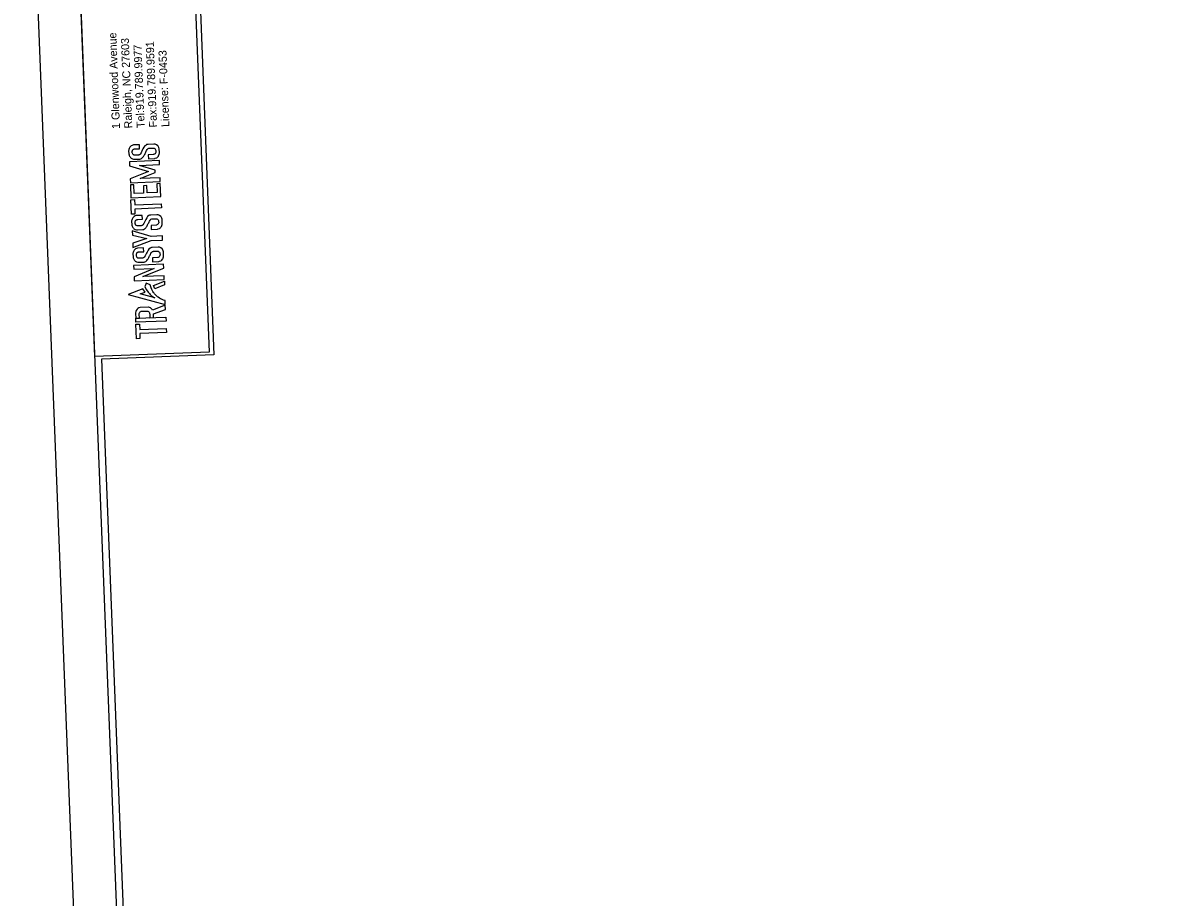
# Model space of a CAD drawing. Extents: x 1627855 to 1629021, y 762567 to 764488.
# Drawn here: x 1627855 to 1628524, y 763528 to 764036 of the extents above; entities that cross this region are included whole.
import ezdxf

# ---------------------------------------------------------------- set-up
doc = ezdxf.new("R2010")
doc.units = 0
for name, color, linetype in [('Old_Level_2', 7, 'Continuous'), ('Old_Level_58', 7, 'Continuous'), ('Sheet Clip Boundary CELL', 7, 'Continuous'), ('Sheet Plan And Profile CELL', 7, 'Continuous'), ('Sheet Plot Border Outside CELL', 7, 'Continuous')]:
    doc.layers.add(name, color=color, linetype=linetype)

msp = doc.modelspace()

# ---------------------------------------------------------------- linework, layer by layer
at = {"layer": 'Old_Level_2'}
for points in [[(1627922.95, 763963.2), (1627922.86, 763965.51), (1627919.39, 763965.37), (1627918.69, 763965.15), (1627918.11, 763964.85), (1627917.73, 763964.53), (1627917.4, 763964.15), (1627917.13, 763963.7), (1627916.97, 763963.27), (1627916.97, 763963.27), (1627916.8, 763962.8), (1627916.7, 763962.31), (1627916.63, 763961.99), (1627916.73, 763960.24), (1627916.85, 763959.72), (1627916.94, 763959.27), (1627917.2, 763958.81), (1627917.43, 763958.42), (1627917.73, 763958.03), (1627918.05, 763957.74), (1627918.43, 763957.51), (1627918.83, 763957.33), (1627919.54, 763957.1), (1627920.05, 763957.07), (1627923.22, 763957.2), (1627923.69, 763957.33), (1627924.17, 763957.58), (1627924.57, 763957.89), (1627924.87, 763958.19), (1627925.2, 763958.66), (1627925.53, 763959.12), (1627925.74, 763959.42), (1627925.95, 763959.91), (1627926.15, 763960.4), (1627926.39, 763960.8), (1627926.66, 763961.25), (1627926.9, 763961.79), (1627927.1, 763962.23), (1627927.4, 763962.67), (1627927.68, 763962.99), (1627927.91, 763963.25), (1627928.39, 763963.43), (1627928.68, 763963.53), (1627930.92, 763963.58), (1627931.41, 763963.44), (1627931.84, 763963.22), (1627932.14, 763962.9), (1627932.32, 763962.55), (1627932.4, 763962.21), (1627932.46, 763961.25), (1627932.38, 763960.93), (1627932.2, 763960.59), (1627932.02, 763960.25), (1627931.69, 763960.1), (1627931.36, 763959.94), (1627931.1, 763959.82), (1627927.99, 763959.66), (1627928.11, 763957.33), (1627931.82, 763957.52), (1627932.09, 763957.64), (1627932.94, 763957.95), (1627933.23, 763958.14), (1627933.54, 763958.4), (1627933.9, 763958.79), (1627934.08, 763959.11), (1627934.24, 763959.55), (1627934.3, 763959.71), (1627934.47, 763960.15), (1627934.5, 763960.68), (1627934.52, 763961.08), (1627934.39, 763963.21), (1627934.22, 763963.8), (1627933.81, 763964.61), (1627933.68, 763964.89), (1627932.86, 763965.48), (1627932.06, 763965.78), (1627931.35, 763965.91), (1627927.93, 763965.72), (1627927.46, 763965.69), (1627927.09, 763965.55), (1627926.74, 763965.34), (1627926, 763964.77), (1627925.48, 763964.04), (1627924.94, 763963.05), (1627924.52, 763962.29), (1627923.81, 763960.79), (1627923.28, 763960.02), (1627922.87, 763959.67), (1627922.59, 763959.58), (1627922.31, 763959.49), (1627919.88, 763959.44), (1627919.62, 763959.56), (1627919.36, 763959.67), (1627919.2, 763959.84), (1627919, 763960.07), (1627918.88, 763960.32), (1627918.76, 763960.58), (1627918.79, 763960.72), (1627918.71, 763960.74), (1627918.69, 763961.7), (1627918.79, 763961.98), (1627918.89, 763962.26), (1627918.98, 763962.54), (1627919.17, 763962.68), (1627919.44, 763962.87), (1627919.72, 763962.98), (1627919.99, 763963.08), (1627920.29, 763963.08)], [(1627928.18, 763949.87), (1627917.41, 763945.63), (1627917.61, 763943.43), (1627935.05, 763944.2), (1627934.96, 763946.31), (1627923.29, 763945.79), (1627932.14, 763949.41), (1627932.12, 763950.76), (1627922.88, 763953.46), (1627934.59, 763953.97), (1627934.49, 763956.25), (1627917.08, 763955.5), (1627917.18, 763953.2)], [(1627917.63, 763942.08), (1627917.92, 763934.7), (1627935.34, 763935.4), (1627935.03, 763942.86), (1627933.07, 763942.79), (1627933.27, 763937.74), (1627927.43, 763937.51), (1627927.26, 763941.72), (1627925.19, 763941.64), (1627925.36, 763937.39), (1627919.87, 763937.17), (1627919.66, 763942.18)], [(1627918.3, 763925.02), (1627917.96, 763933.48), (1627920.04, 763933.56), (1627920.16, 763930.45), (1627935.57, 763931.07), (1627935.67, 763928.73), (1627920.15, 763928.1), (1627920.27, 763925.13)], [(1627924.61, 763922.11), (1627924.52, 763924.41), (1627921.05, 763924.27), (1627920.35, 763924.05), (1627919.77, 763923.75), (1627919.39, 763923.43), (1627919.06, 763923.05), (1627918.79, 763922.6), (1627918.63, 763922.17), (1627918.63, 763922.17), (1627918.46, 763921.7), (1627918.36, 763921.21), (1627918.29, 763920.89), (1627918.39, 763919.14), (1627918.51, 763918.62), (1627918.6, 763918.17), (1627918.86, 763917.71), (1627919.09, 763917.32), (1627919.39, 763916.94), (1627919.71, 763916.64), (1627920.09, 763916.41), (1627920.49, 763916.23), (1627921.19, 763916.01), (1627921.71, 763915.97), (1627924.88, 763916.1), (1627925.35, 763916.23), (1627925.83, 763916.48), (1627926.23, 763916.79), (1627926.53, 763917.1), (1627926.86, 763917.56), (1627927.19, 763918.03), (1627927.4, 763918.32), (1627927.6, 763918.81), (1627927.81, 763919.3), (1627928.05, 763919.7), (1627928.32, 763920.15), (1627928.56, 763920.69), (1627928.76, 763921.13), (1627929.06, 763921.57), (1627929.34, 763921.9), (1627929.57, 763922.16), (1627930.05, 763922.33), (1627930.34, 763922.43), (1627932.58, 763922.49), (1627933.07, 763922.34), (1627933.5, 763922.12), (1627933.8, 763921.8), (1627933.98, 763921.45), (1627934.06, 763921.11), (1627934.12, 763920.15), (1627934.04, 763919.83), (1627933.86, 763919.49), (1627933.68, 763919.16), (1627933.35, 763919), (1627933.02, 763918.84), (1627932.76, 763918.72), (1627929.65, 763918.56), (1627929.77, 763916.23), (1627933.48, 763916.42), (1627933.75, 763916.55), (1627934.6, 763916.85), (1627934.89, 763917.04), (1627935.2, 763917.3), (1627935.56, 763917.7), (1627935.74, 763918.01), (1627935.9, 763918.45), (1627935.96, 763918.61), (1627936.13, 763919.05), (1627936.16, 763919.58), (1627936.18, 763919.98), (1627936.04, 763922.12), (1627935.88, 763922.7), (1627935.47, 763923.51), (1627935.34, 763923.79), (1627934.52, 763924.38), (1627933.72, 763924.68), (1627933.01, 763924.81), (1627929.59, 763924.62), (1627929.12, 763924.59), (1627928.75, 763924.45), (1627928.4, 763924.24), (1627927.66, 763923.67), (1627927.14, 763922.94), (1627926.59, 763921.95), (1627926.18, 763921.19), (1627925.47, 763919.69), (1627924.94, 763918.92), (1627924.53, 763918.57), (1627924.25, 763918.48), (1627923.97, 763918.4), (1627921.54, 763918.35), (1627921.28, 763918.46), (1627921.02, 763918.57), (1627920.86, 763918.75), (1627920.66, 763918.97), (1627920.54, 763919.22), (1627920.42, 763919.48), (1627920.45, 763919.63), (1627920.37, 763919.64), (1627920.35, 763920.6), (1627920.45, 763920.88), (1627920.55, 763921.16), (1627920.64, 763921.44), (1627920.83, 763921.58), (1627921.1, 763921.77), (1627921.38, 763921.88), (1627921.65, 763921.98), (1627921.95, 763921.98)], [(1627918.99, 763908.27), (1627919.09, 763905.74), (1627929.82, 763909.78), (1627936.36, 763910.07), (1627936.25, 763912.46), (1627929.77, 763912.17), (1627918.67, 763915.39), (1627918.84, 763912.91), (1627927.26, 763910.93)], [(1627925.38, 763903.25), (1627925.28, 763905.56), (1627921.81, 763905.42), (1627921.11, 763905.19), (1627920.53, 763904.89), (1627920.15, 763904.58), (1627919.82, 763904.19), (1627919.55, 763903.74), (1627919.39, 763903.31), (1627919.39, 763903.31), (1627919.22, 763902.85), (1627919.12, 763902.36), (1627919.05, 763902.03), (1627919.16, 763900.29), (1627919.27, 763899.76), (1627919.36, 763899.31), (1627919.62, 763898.86), (1627919.85, 763898.46), (1627920.15, 763898.08), (1627920.47, 763897.78), (1627920.85, 763897.55), (1627921.25, 763897.37), (1627921.96, 763897.15), (1627922.47, 763897.12), (1627925.64, 763897.24), (1627926.11, 763897.38), (1627926.59, 763897.63), (1627926.99, 763897.93), (1627927.29, 763898.24), (1627927.62, 763898.7), (1627927.95, 763899.17), (1627928.16, 763899.46), (1627928.37, 763899.95), (1627928.57, 763900.45), (1627928.81, 763900.84), (1627929.08, 763901.3), (1627929.32, 763901.83), (1627929.52, 763902.28), (1627929.82, 763902.72), (1627930.11, 763903.04), (1627930.33, 763903.3), (1627930.81, 763903.47), (1627931.1, 763903.58), (1627933.34, 763903.63), (1627933.83, 763903.49), (1627934.26, 763903.26), (1627934.56, 763902.94), (1627934.74, 763902.59), (1627934.82, 763902.26), (1627934.88, 763901.3), (1627934.8, 763900.97), (1627934.62, 763900.63), (1627934.44, 763900.3), (1627934.11, 763900.14), (1627933.78, 763899.99), (1627933.52, 763899.86), (1627930.41, 763899.71), (1627930.53, 763897.37), (1627934.24, 763897.56), (1627934.51, 763897.69), (1627935.36, 763897.99), (1627935.65, 763898.18), (1627935.96, 763898.44), (1627936.32, 763898.84), (1627936.5, 763899.15), (1627936.66, 763899.59), (1627936.72, 763899.75), (1627936.89, 763900.19), (1627936.92, 763900.73), (1627936.94, 763901.12), (1627936.81, 763903.26), (1627936.64, 763903.85), (1627936.23, 763904.66), (1627936.1, 763904.93), (1627935.28, 763905.52), (1627934.48, 763905.82), (1627933.77, 763905.95), (1627930.35, 763905.76), (1627929.88, 763905.74), (1627929.51, 763905.59), (1627929.16, 763905.39), (1627928.43, 763904.82), (1627927.9, 763904.09), (1627927.36, 763903.09), (1627926.94, 763902.33), (1627926.23, 763900.84), (1627925.7, 763900.06), (1627925.29, 763899.72), (1627925.01, 763899.63), (1627924.73, 763899.54), (1627922.3, 763899.49), (1627922.04, 763899.6), (1627921.78, 763899.72), (1627921.62, 763899.89), (1627921.42, 763900.11), (1627921.3, 763900.37), (1627921.18, 763900.62), (1627921.21, 763900.77), (1627921.13, 763900.78), (1627921.11, 763901.74), (1627921.21, 763902.02), (1627921.31, 763902.3), (1627921.41, 763902.58), (1627921.59, 763902.72), (1627921.86, 763902.92), (1627922.14, 763903.02), (1627922.41, 763903.12), (1627922.71, 763903.13)], [(1627919.87, 763886.32), (1627937.31, 763887.03), (1627937.22, 763889.26), (1627924.95, 763888.76), (1627937.07, 763893.7), (1627936.95, 763895.95), (1627919.46, 763895.23), (1627919.55, 763893.06), (1627931.52, 763893.54), (1627919.77, 763888.68)], [(1627916.36, 763878.41), (1627937.94, 763872.59), (1627937.84, 763874.81), (1627936.99, 763875.12), (1627935.81, 763875.64), (1627935.17, 763875.93), (1627934.61, 763876.28), (1627933.83, 763876.78), (1627933.35, 763877.09), (1627932.95, 763877.45), (1627932.54, 763877.82), (1627932.02, 763878.28), (1627931.74, 763878.68), (1627931.39, 763879.08), (1627931.05, 763879.63), (1627930.75, 763880.11), (1627930.13, 763881.3), (1627929.68, 763882.28), (1627929.06, 763883.9), (1627926.87, 763884.95), (1627926, 763882.74), (1627926.95, 763881.15), (1627927.91, 763879.81), (1627928.75, 763878.86), (1627929.19, 763878.35), (1627929.78, 763877.84), (1627930.37, 763877.33), (1627930.81, 763876.95), (1627931.47, 763876.6), (1627931.84, 763876.4), (1627923.36, 763878.7), (1627926.21, 763879.81), (1627924.88, 763881.65)], [(1627931.95, 763881.64), (1627931.11, 763883.52), (1627937.45, 763886.04), (1627937.46, 763883.94)], [(1627922.84, 763864.63), (1627922.75, 763867.01), (1627922.79, 763867.32), (1627922.93, 763867.73), (1627923.14, 763868.06), (1627923.4, 763868.3), (1627923.72, 763868.47), (1627923.98, 763868.6), (1627924.56, 763868.62), (1627927.04, 763868.73), (1627927.38, 763868.68), (1627927.83, 763868.62), (1627928.12, 763868.5), (1627928.39, 763868.31), (1627928.61, 763868.05), (1627928.78, 763867.63), (1627928.84, 763867.3), (1627928.89, 763866.98), (1627928.99, 763864.88), (1627931.09, 763864.97), (1627931, 763867.07), (1627938.06, 763869.72), (1627937.94, 763872.14), (1627930.51, 763869.19), (1627930.36, 763869.57), (1627929.94, 763870.09), (1627929.39, 763870.55), (1627928.74, 763870.88), (1627928.1, 763871.06), (1627927.92, 763871.04), (1627923.35, 763870.9), (1627922.62, 763870.67), (1627921.95, 763870.28), (1627921.5, 763869.86), (1627921.05, 763869.14), (1627920.85, 763868.45), (1627920.65, 763867.77), (1627920.67, 763867.36), (1627920.76, 763864.54)], [(1627920.85, 763862.23), (1627920.76, 763864.54), (1627938.31, 763865.25), (1627938.4, 763862.94)], [(1627921.23, 763852.62), (1627920.89, 763861.08), (1627922.96, 763861.16), (1627923.08, 763858.05), (1627938.49, 763858.67), (1627938.59, 763856.33), (1627923.08, 763855.7), (1627923.2, 763852.73)]]:
    msp.add_lwpolyline(points, close=True, dxfattribs=at)
at = {"layer": 'Old_Level_58'}
msp.add_lwpolyline([(1627896.85, 763842.26), (1627888.97, 764042.15), (1627955.61, 764044.78), (1627963.49, 763844.89)], close=True, dxfattribs=at)
at = {"layer": 'Sheet Clip Boundary CELL'}
msp.add_lwpolyline([(1628522.47, 764228.52), (1628282.65, 764219.07), (1628066.45, 764210.34), (1628072.87, 764047.54), (1627958.4, 764043.02), (1627966.27, 763843.29), (1627900.75, 763840.71), (1627941.6, 762804.67), (1628337.82, 762820.15), (1628577.63, 762829.61), (1628634.82, 762831.83), (1628637.13, 762773.12), (1628655.42, 762773.84), (1628653.1, 762832.57), (1628984.86, 762845.59), (1628929.69, 764244.53)], close=True, dxfattribs=at)
at = {"layer": 'Sheet Plan And Profile CELL'}
msp.add_lwpolyline([(1627881.09, 764242.05), (1627940.19, 762743.21), (1628989.38, 762784.59), (1628930.27, 764283.42)], close=True, dxfattribs=at)
at = {"layer": 'Sheet Plot Border Outside CELL'}
msp.add_lwpolyline([(1629021.25, 762610.71), (1628954.27, 764309.39), (1627855.12, 764266.04), (1627922.11, 762567.36)], close=True, dxfattribs=at)

# ---------------------------------------------------------------- texts
at = {"layer": 'Old_Level_2'}
for s, p in [('1 Glenwood Avenue', (1627911.61, 763974.79)), ('Raleigh, NC 27603', (1627918.8, 763975.08)), ('Tel:919.789.9977 ', (1627925.99, 763975.36)), ('Fax:919.789.9591', (1627933.18, 763975.64)), ('License: F-0453', (1627940.37, 763975.93))]:
    msp.add_text(s, height=4.6576, rotation=92.25819, dxfattribs=at).set_placement(p)

doc.saveas('drawing.dxf')
